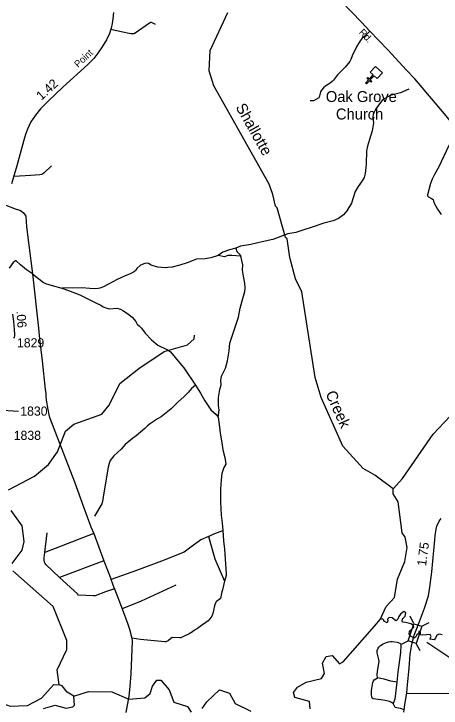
# Model space of a CAD drawing. Extents: x 2104537 to 2336408, y 34176 to 229611.
# Drawn here: x 2200536 to 2206373, y 68278 to 77773 of the extents above; entities that cross this region are included whole.
import ezdxf

# ---------------------------------------------------------------- set-up
doc = ezdxf.new("R2010")
doc.units = 0
for name, color, linetype in [('Exist Cultural Church CELL', 7, 'Continuous'), ('Exist Cultural Church Label', 7, 'Continuous'), ('Exist Hydrographic Creek Single Shore', 7, 'Continuous'), ('Exist Hydrographic Misc Water Feature', 7, 'Continuous'), ('Exist Road Non-System Type 51', 7, 'Continuous'), ('Exist Road Primary NC Attributed', 7, 'Continuous'), ('Exist Road Primary NC Label', 7, 'Continuous'), ('Exist Road Secondary Mileage Hundredths English Label', 7, 'Continuous'), ('Exist Road Secondary Structure Standard Bridge CELL', 7, 'Continuous'), ('Exist Road Secondary Structure Standard Bridge Number Label', 7, 'Continuous'), ('Exist Road Secondary Type 51 Attributed', 7, 'Continuous'), ('Exist Road Secondary Type 51 Label', 7, 'Continuous'), ('Exist Road Secondary Type 51 Number Label', 7, 'Continuous'), ('Old_Level_32', 7, 'Continuous')]:
    doc.layers.add(name, color=color, linetype=linetype)

msp = doc.modelspace()

# ---------------------------------------------------------------- linework, layer by layer
at = {"layer": 'Exist Cultural Church CELL'}
msp.add_lwpolyline([(2205498.5, 76887.3), (2205456.9, 76926.3), (2205404.7, 76870.8), (2205428, 76848.9), (2205417.1, 76837.3), (2205393.8, 76859.2), (2205352.6, 76815.4), (2205340.9, 76826.4), (2205382.1, 76870.2), (2205358.8, 76892.1), (2205369.8, 76903.7), (2205393.1, 76881.8), (2205445.3, 76937.3), (2205403.4, 76976.9), (2205476.3, 77054.4), (2205571.4, 76964.8)], close=True, dxfattribs=at)
at = {"layer": 'Exist Hydrographic Creek Single Shore'}
msp.add_line((2205460.9, 69399.7), (2205539.8, 69490.8), dxfattribs=at)
for points in [[(2205719.8, 71275.4), (2205467.8, 71464), (2205308.9, 71555.6), (2205031.9, 71859.5), (2204735.8, 72524.6), (2204650.9, 72798.6), (2204467.8, 73973.4), (2204383.9, 74148.9), (2204305.8, 74439), (2204270.9, 74695.6), (2204245.9, 74712.6), (2204134.8, 75121.5), (2204109.8, 75144.9), (2204074.9, 75303.1), (2204023.8, 75445.1), (2203265.8, 76788.5), (2203205.9, 76996.3), (2203219.8, 77271.7), (2203458.9, 77792)], [(2205539.8, 69490.8), (2205621.8, 69666.4), (2205737.9, 69792.2), (2205777.9, 70040.7), (2205875.9, 70284.9), (2205907.9, 70474.5), (2205881.8, 70616.1), (2205840, 70676), (2205787.9, 71100.2), (2205719.8, 71206.5), (2205719.8, 71275.4)], [(2206385.7, 69278), (2206350, 69288.8), (2206316, 69274.5), (2206296.3, 69233.3), (2206278.4, 69213.6), (2206217.6, 69219), (2206237.3, 69256.6), (2206222.9, 69283.4), (2206174.6, 69278), (2206117.4, 69274.5), (2206090.6, 69278), (2206092.4, 69306.7), (2206081.6, 69331.7), (2206067.3, 69326.4), (2206062, 69297.7), (2206040.5, 69279.8), (2206028, 69253), (2206004.7, 69233.3), (2205961.8, 69256.6), (2205936.7, 69285.2), (2205942.1, 69328.2), (2205976.1, 69362.2), (2205999.3, 69383.6), (2205994, 69408.7), (2205958.2, 69432), (2205888.4, 69448.1), (2205845.5, 69455.2), (2205840.1, 69467.8), (2205845.5, 69500), (2205881.3, 69534), (2205890.2, 69578.7), (2205863.4, 69598.4), (2205816.9, 69562.6), (2205795.4, 69528.6), (2205782.9, 69492.8), (2205757.8, 69469.6), (2205734.6, 69485.7), (2205702.4, 69514.3), (2205661.3, 69516.1), (2205641.6, 69494.6), (2205643.4, 69469.6), (2205636.2, 69444.5), (2205598.6, 69464.2), (2205587.9, 69483.9), (2205571.8, 69500), (2205539.8, 69490.8)], [(2204581.8, 68265.9), (2204573, 68367.7), (2204372.8, 68424.1), (2204355.8, 68490.1), (2204412.8, 68564.4), (2204529.9, 68634.4), (2204737.8, 68682.8), (2204778.8, 68750.9), (2204752.8, 68892.5), (2204801.8, 68983.4), (2204885.9, 68995), (2204986, 68884.8), (2205036, 68910), (2205460.9, 69399.7)], [(2201356.7, 68442.9), (2201555.8, 68504.7), (2201872.9, 68498.5), (2202106.8, 68398.9), (2202322.9, 68417.7), (2202397.8, 68475.3), (2202429.8, 68576.4), (2202487.8, 68660.6), (2202545.8, 68659.4), (2202655.9, 68529.4), (2202722.8, 68360.8), (2202906.9, 68298.2), (2202957.8, 68221.7)], [(2199594.7, 67682.9), (2199728.8, 67726.3), (2199877.9, 67851.3), (2199992.7, 67983.6), (2200025.7, 68084.7), (2200031.9, 68478.3), (2200097.7, 68526.2), (2200222.8, 68471.3), (2200331.9, 68360.9), (2200482.8, 68305.5), (2200723.7, 68314), (2200914.8, 68415.3), (2201079.9, 68599.1), (2201155.8, 68594.4)], [(2201356.7, 68442.9), (2201264.9, 68493.9), (2201196.8, 68583.7), (2201155.8, 68594.4)], [(2203106.9, 68274.6), (2203172.9, 68365.2), (2203346.8, 68525.9), (2203480.9, 68484), (2203556.9, 68341.4), (2203773.9, 68235.6)]]:
    msp.add_lwpolyline(points, dxfattribs=at)
at = {"layer": 'Exist Hydrographic Misc Water Feature'}
for points in [[(2205719.8, 71275.4), (2205843.9, 71417.4), (2206263.8, 72026), (2206496, 72270.9), (2206860.9, 72513.2), (2207050.8, 72749), (2207522.9, 73077.9), (2208394.9, 73543.3), (2209201, 73846)], [(2200461.9, 71262), (2200818.9, 71448.7), (2201009.8, 71609), (2201133.8, 71783.8), (2201239.9, 72067.2), (2201355.9, 72160.1), (2201737.7, 72297.1), (2201836.8, 72423.1), (2201984.8, 72715.5), (2202241.7, 72923.8), (2202590.7, 73153.3), (2202906.9, 73245.6), (2202997.8, 73329.1), (2203005.8, 73378.2)], [(2200510.9, 70253.8), (2200650.7, 70438.1), (2200674.7, 70555.8), (2200648.9, 70772.8), (2200497.8, 70979.1)], [(2201155.8, 68594.4), (2201128.9, 68801.6), (2201259.7, 69077.9), (2201259.7, 69202.6), (2201072.7, 69665.6), (2200519.7, 70155.2)], [(2200940.9, 68273.7), (2201098.8, 68316.6), (2201248.9, 68277.7), (2201340.7, 68295.5), (2201365.8, 68318), (2201356.7, 68442.9)]]:
    msp.add_lwpolyline(points, dxfattribs=at)
at = {"layer": 'Exist Road Non-System Type 51'}
for p, q in [((2200741.2, 74609.7), (2200789.1, 74219.1)), ((2200957.3, 70405.6), (2200991.7, 70676.2)), ((2201626, 70664.3), (2200957.3, 70405.6)), ((2201626, 70664.3), (2201762.8, 70292)), ((2201762.8, 70292), (2201157.7, 70064.5)), ((2201762.8, 70292), (2201866.5, 70035.4)), ((2201912.3, 69908.2), (2201866.5, 70035.4)), ((2201912.3, 69908.2), (2202013.7, 69637.5))]:
    msp.add_line(p, q, dxfattribs=at)
for points in [[(2202470.6, 77628.9), (2202417.4, 77656.2), (2202403.6, 77656.1), (2202178.1, 77501), (2202167.9, 77498.6), (2202134.2, 77500.5), (2202001.5, 77526.7), (2201861, 77559)], [(2205398.3, 77538.9), (2205329.3, 77468.1), (2205295.6, 77439.6), (2205268, 77403), (2205217.2, 77320.7), (2205158.8, 77199.7), (2205138.4, 77147.3), (2205124.5, 77123.6), (2205062.9, 77042.5), (2204958.3, 76941.2), (2204901, 76864.5), (2204885.3, 76848.1), (2204857.6, 76826), (2204797.9, 76789.1), (2204766.5, 76762.8), (2204737, 76728.2), (2204725.1, 76708.1), (2204707.9, 76634.3), (2204702.2, 76623.9), (2204630.5, 76585), (2204584.9, 76582.2)], [(2205933, 76742.8), (2205818.2, 76692.7), (2205676.8, 76655.3), (2205572.1, 76596.3), (2205481.9, 76474.8), (2205445.1, 76403.5), (2205439.5, 76354.4), (2205447.3, 76280.9), (2205430.6, 76172.8), (2205396.1, 76054.6), (2205367.1, 75965.5), (2205353.8, 75902), (2205347.1, 75719.7), (2205343.7, 75672.9), (2205337.1, 75591.6), (2205320.4, 75534.7), (2205294.7, 75487.9), (2205239, 75409.9), (2205197.8, 75342.5), (2205146.6, 75184.2), (2205085.3, 75077.2), (2205040.8, 75024.9), (2204969.5, 74972.5), (2204899.3, 74942.4), (2204771.2, 74910.1), (2204612, 74855.4), (2204483.9, 74814.2), (2204387, 74783), (2204277.8, 74762.9), (2204075.1, 74689.4), (2203925.8, 74654.3), (2203771, 74620.8), (2203631.8, 74597.4), (2203568.3, 74568.5)], [(2206686.2, 76069.6), (2206596.8, 76028.3), (2206509.2, 75993.3), (2206485.3, 75979), (2206467.5, 75956.7), (2206442.3, 75896.5), (2206343, 75679.2), (2206282.3, 75578.4), (2206251.3, 75514), (2206228.1, 75453.8), (2206207.4, 75365.6), (2206186, 75297.1), (2206186.5, 75285), (2206199.7, 75272.9), (2206242.9, 75250.1), (2206262.3, 75235.6), (2206275.6, 75194.3), (2206300.2, 75144.6), (2206325, 75100.9), (2206373.8, 75027.7)], [(2201047.5, 75696.7), (2200950.9, 75599.2), (2200924.9, 75581), (2200911.1, 75576.7), (2200889, 75572.5), (2200761.1, 75560.9), (2200537.5, 75548.1)], [(2200426.6, 75156.6), (2200567.3, 75102.3), (2200616.2, 75086.3), (2200637.6, 75073.4), (2200666, 75051.6), (2200690.4, 75021.9), (2200697.3, 75004.4), (2200710.3, 74862.4), (2200741.2, 74609.7)], [(2203568.3, 74568.5), (2203480.3, 74547.3), (2203392.9, 74514.6), (2203324.9, 74468.1)], [(2203568.3, 74568.5), (2203583.9, 74523.9), (2203628.4, 74477.1), (2203638.3, 74459.8)], [(2203324.9, 74468.1), (2203228.7, 74438.3), (2203150.8, 74421.7), (2203029.8, 74418.4), (2202903.4, 74366.7), (2202804.1, 74337.4), (2202698.3, 74309.9), (2202640.4, 74303.2), (2202601.3, 74301.6), (2202552.4, 74302.3), (2202502.4, 74309.5), (2202426, 74331.3), (2202413.7, 74336.1), (2202375.7, 74360.4), (2202355.8, 74364.4), (2202325.5, 74359.1), (2202267.6, 74334.3), (2202216.3, 74292), (2202196.7, 74263.5), (2202181.7, 74248.1), (2202169, 74239.1), (2202115.3, 74212.3), (2202055.6, 74191.8), (2201946.3, 74140.4), (2201761.3, 74041.9), (2201709.8, 74021.3), (2201685.7, 74014.8), (2201631.9, 74013.3), (2201459.8, 74024.1), (2201191.4, 74022.4)], [(2203638.3, 74459.8), (2203512.3, 74466.5), (2203459.2, 74466.5), (2203414.4, 74449.9), (2203324.9, 74468.1)], [(2203326.6, 72256.8), (2203331.5, 72288.3), (2203341.5, 72359.6), (2203331.5, 72411), (2203331.5, 72523.8), (2203349.8, 72635), (2203368, 72700.5), (2203364.7, 72758.6), (2203373, 72818.3), (2203426, 72926.1), (2203452.6, 73025.7), (2203475.8, 73163.4), (2203485.7, 73268.7), (2203605.1, 73625.4), (2203628.3, 73746.5), (2203653.2, 73847.7), (2203691.3, 73973.8), (2203696.3, 74020.2), (2203691.3, 74089.9), (2203674.7, 74186.1), (2203659.8, 74265.7), (2203664.8, 74338.7), (2203638.3, 74459.8)], [(2200789.1, 74219.1), (2200708.1, 74272.2), (2200627.3, 74339.1), (2200568.4, 74394.3), (2200558.2, 74394.2), (2200538, 74383.8), (2200524.6, 74371.5), (2200472, 74295.1)], [(2200789.1, 74219.1), (2200942.6, 74099.4), (2200968.9, 74083.8), (2201059.2, 74056.8), (2201191.4, 74022.4)], [(2200789.1, 74219.1), (2200870.9, 73476.4), (2200884.1, 73327.2), (2200920.6, 73027), (2200961.9, 72635.8), (2200970.4, 72583.8), (2200970.8, 72549.7), (2200977.8, 72489.8), (2200999.6, 72360.1), (2201014.6, 72290.3), (2201027.2, 72245.1), (2201246.6, 71677.5), (2201362.7, 71370.9), (2201485.1, 71030.6), (2201586.8, 70757.9), (2201626, 70664.3)], [(2201191.4, 74022.4), (2201282, 73991.8), (2201435, 73929.8), (2201507.5, 73892.6), (2201582, 73859.4), (2201656.4, 73822.5), (2201722.6, 73787.4), (2201757.3, 73765.8), (2201803.5, 73746.5), (2201824.1, 73741.2), (2201839.5, 73740.9), (2201943.3, 73746.4), (2201974.4, 73740.6), (2201991.6, 73734.7), (2202023.8, 73717.3), (2202089.9, 73677), (2202153.2, 73623), (2202200.7, 73566.9), (2202222, 73531.1), (2202246.7, 73504.4), (2202277.3, 73476.5), (2202330.1, 73407.3), (2202417.2, 73314.4), (2202504.1, 73243.5), (2202633.1, 73179.3), (2202658.1, 73164.4), (2202675.6, 73150), (2202801.5, 72997.3), (2202858.4, 72932.2), (2203015.9, 72696.2)], [(2203015.9, 72696.2), (2202964.1, 72647.7), (2202923.8, 72600.9), (2202855.9, 72534.3), (2202778.5, 72467.2), (2202685.8, 72369.9), (2202549.2, 72262.3), (2202497.4, 72233.5), (2202400.5, 72172.3), (2202360.8, 72139.6), (2202323.3, 72101.3), (2202265.9, 72050.6), (2202204.6, 72001.6), (2202155, 71965.1), (2202054, 71883.8), (2202001, 71821.1), (2201902.1, 71727.9), (2201852.6, 71665.2), (2201836.1, 71622.2), (2201822.3, 71571), (2201765, 71220.1), (2201748.3, 71101.9), (2201738.8, 71069.6), (2201638.8, 70904.6)], [(2203015.9, 72696.2), (2203085, 72587.3), (2203144.6, 72482.1), (2203226.2, 72359.2), (2203298.4, 72291.6), (2203326.6, 72256.8)], [(2203326.6, 72256.8), (2203343.1, 72119.9), (2203356.4, 72038.6), (2203378, 71907.5), (2203392.9, 71811.3), (2203419.4, 71706.8), (2203427.7, 71647.9), (2203429.4, 71614.7), (2203406.1, 71569.9), (2203377, 71486.2), (2203368.8, 71400.7), (2203358.5, 71270.7), (2203356.8, 71098.8), (2203369.3, 70916.8), (2203382.7, 70808.9), (2203390.7, 70707)], [(2203195.8, 70626.7), (2203258.8, 70658.2), (2203390.7, 70707)], [(2203390.7, 70707), (2203401.9, 70563.5), (2203413.5, 70451.4), (2203435.9, 70113.7), (2203434.1, 70089.8), (2203415.6, 70015.2)], [(2203195.8, 70626.7), (2203088.5, 70577.3), (2202969.4, 70493.8), (2202863.8, 70410.3), (2202782.1, 70378), (2202589.7, 70301.3), (2202210, 70159.9), (2201866.5, 70035.4)], [(2203195.8, 70626.7), (2203282.6, 70317.5), (2203415.6, 70015.2)], [(2201157.7, 70064.5), (2200973.5, 70243.9), (2200963.3, 70257.8), (2200955.1, 70275.7), (2200951.2, 70294.5), (2200950.3, 70331.6), (2200957.3, 70405.6)], [(2201912.3, 69908.2), (2201786.8, 69866.3), (2201647.3, 69813.9), (2201619.4, 69812.1), (2201417.2, 69823.9), (2201404.7, 69839.5), (2201157.7, 70064.5)], [(2203415.6, 70015.2), (2203386.4, 69897.1), (2203377, 69867.1), (2203359.2, 69777.6), (2203354.5, 69771.1), (2203302.9, 69736), (2203296.9, 69727.9), (2203275.5, 69675.9), (2203255.1, 69569.6), (2203239.4, 69537.4), (2203212.1, 69497), (2203188.6, 69469.9), (2203158.6, 69446.5), (2203101.1, 69407.6), (2203043.8, 69364.7), (2203003.7, 69342.5), (2202976.4, 69319.8), (2202930.5, 69291.4), (2202845.1, 69251.1), (2202815.4, 69239.9), (2202803.2, 69237.8), (2202696.7, 69242.5), (2202679.4, 69232), (2202641.7, 69197.6), (2202612.9, 69184.4), (2202598.7, 69183), (2202265.4, 69216.7), (2202147.3, 69233.4)], [(2202747.9, 69959), (2202276.5, 69740.7), (2202013.7, 69637.5)], [(2202013.7, 69637.5), (2202094.5, 69424.4), (2202117.5, 69357), (2202147.3, 69233.4)], [(2202147.3, 69233.4), (2202153.7, 69191.3), (2202133.6, 68747.1), (2202121.8, 68573.1), (2202104.8, 68443.2), (2202067.5, 68218.9)], [(2205503.3, 68692.6), (2205500.5, 68736.7), (2205504.2, 68776.6), (2205526.3, 68918.9), (2205519.5, 68958.7), (2205499, 69034.9), (2205499.6, 69063.8), (2205511.8, 69099), (2205521.5, 69112.9), (2205545.2, 69133.1), (2205582.7, 69155.3), (2205624.8, 69176.2), (2205653.5, 69186.1), (2205681.8, 69189.9), (2205703.1, 69188.8), (2205774.8, 69178.2), (2205807.3, 69164.5), (2205816.7, 69158.1), (2205820.8, 69151.7), (2205821.7, 69126.8), (2205821.1, 69104.9)], [(2205816, 69037.1), (2205780, 68770.3), (2205770.1, 68632.4)], [(2205821.1, 69104.9), (2205820.2, 69068.7), (2205816, 69037.1)], [(2205715.7, 68341.3), (2205694.7, 68352.7), (2205665.6, 68367.2), (2205608.9, 68380.2), (2205549.1, 68389.9), (2205446.9, 68406), (2205433, 68415.8), (2205427.3, 68426.7), (2205422.4, 68461.6), (2205423.5, 68517.7), (2205438.1, 68629.9), (2205447.7, 68652.1), (2205459.5, 68666.3), (2205503.3, 68692.6)], [(2205770.1, 68632.4), (2205711.9, 68639.4), (2205686.1, 68645.2), (2205595.4, 68674.1), (2205503.3, 68692.6)], [(2205770.1, 68632.4), (2205741.1, 68402), (2205715.7, 68341.3)], [(2205904, 68484.1), (2206556.4, 68478.1), (2206698, 68476)], [(2205869.1, 68253.3), (2205816, 68271.7), (2205791.8, 68276.6), (2205765.9, 68279.8), (2205746.5, 68284.7), (2205715.7, 68341.3)]]:
    msp.add_lwpolyline(points, dxfattribs=at)
at = {"layer": 'Exist Road Primary NC Attributed'}
msp.add_lwpolyline([(2209055.5, 73978.4), (2209037.8, 74012.2), (2208614.2, 74282.8), (2208495.2, 74369.1), (2208293.4, 74488.5), (2208051.3, 74643.4), (2207851.6, 74782.7), (2207754.6, 74855.5), (2207669.3, 74924.4), (2207629, 74961.9), (2207423.6, 75199.1), (2206686.2, 76069.6), (2206439.8, 76378.5), (2206015.2, 76882.7), (2205901.3, 77001.4), (2205643.9, 77280), (2205398.3, 77538.9), (2205284.5, 77661.5), (2204864.8, 78097.8), (2204647.8, 78329)], dxfattribs=at)
at = {"layer": 'Exist Road Secondary Structure Standard Bridge CELL'}
for p, q in [((2206002.3, 69432.1), (2205951.2, 69533.2)), ((2206109.8, 69396.8), (2206210.8, 69447.9)), ((2205823.3, 69145.8), (2205924.4, 69196.8)), ((2206085.4, 69059.7), (2206034.4, 69160.7))]:
    msp.add_line(p, q, dxfattribs=at)
msp.add_lwpolyline([(2205924.4, 69196.8), (2206001.7, 69432.3), (2206111.7, 69396.2), (2206034.4, 69160.7)], close=True, dxfattribs=at)
at = {"layer": 'Exist Road Secondary Structure Standard Bridge Number Label'}
msp.add_line((2206177.6, 69177.4), (2206892.7, 68704.9), dxfattribs=at)
at = {"layer": 'Exist Road Secondary Type 51 Attributed'}
for points in [[(2201898.9, 77793.9), (2201889, 77704.8), (2201879.1, 77641.6), (2201865.2, 77576), (2201841.5, 77504.9), (2201800.1, 77416.3), (2201742.6, 77321.2), (2201683.2, 77234.1), (2201627.8, 77164.7), (2201546.6, 77079.6), (2201204, 76768.5), (2201003.9, 76580.1), (2200901.1, 76475.1), (2200829.8, 76389.9), (2200798.1, 76344.4), (2200768.4, 76294.9), (2200720.9, 76196.1), (2200693.6, 76124.2), (2200671.4, 76043.7), (2200576.3, 75695), (2200501.1, 75449.3)], [(2200516.2, 73663.7), (2200529.6, 73564), (2200541.7, 73455.9), (2200544, 73386.3), (2200544, 73370.2), (2200537.4, 73349.6), (2200531.9, 73338.6)], [(2205996.8, 69237.6), (2206007.1, 69273.4), (2206051.9, 69390.5), (2206143.9, 69645.8), (2206198.7, 69813.1), (2206219.4, 69933.4), (2206244.5, 70143.2), (2206288.3, 70578.1), (2206291.7, 70634.1), (2206304.6, 70726.4), (2206314.2, 70764.6), (2206347.7, 70836.8), (2206375, 70871)], [(2205864.7, 68223.5), (2205884.1, 68353), (2205904.5, 68488.6), (2205914.5, 68596.1), (2205932.4, 68778.2), (2205940.7, 68881.1), (2205946.6, 68957.2), (2205952.4, 69011.9), (2205964.1, 69095.8), (2205970, 69127), (2205987.7, 69206), (2205996.8, 69237.6)]]:
    msp.add_lwpolyline(points, dxfattribs=at)
at = {"layer": 'Exist Road Secondary Type 51 Number Label'}
msp.add_line((2199919.2, 72382.9), (2200598.5, 72337), dxfattribs=at)

# ---------------------------------------------------------------- texts
at = {"layer": 'Exist Cultural Church Label'}
for s, p in [('Oak Grove', (2204798.2, 76567.4)), ('Church', (2204936, 76328.4))]:
    msp.add_text(s, height=150, dxfattribs=at).set_placement(p)
at = {"layer": 'Exist Road Primary NC Label'}
msp.add_text('Rd.', height=95, rotation=313.48542, dxfattribs=at).set_placement((2205243.4, 77513.6))
at = {"layer": 'Exist Road Secondary Mileage Hundredths English Label'}
for s, rotation, p in [('1.42', 42.23693, (2200910.7, 76583.5)), ('.06', 273.53882, (2200571.1, 73706.3)), ('1.75', 82.52042, (2206166.9, 70214.8))]:
    msp.add_text(s, height=125, rotation=rotation, dxfattribs=at).set_placement(p)
at = {"layer": 'Exist Road Secondary Type 51 Label'}
msp.add_text('Point', height=95, rotation=42.7211, dxfattribs=at).set_placement((2201412.9, 77031.8))
at = {"layer": 'Exist Road Secondary Type 51 Number Label'}
for s, p in [('1829', (2200578.4, 73211.6)), ('1830', (2200623.4, 72277.5)), ('1838', (2200533.9, 71945.8))]:
    msp.add_text(s, height=125, dxfattribs=at).set_placement(p)
at = {"layer": 'Old_Level_32'}
for s, rotation, p in [('Shallotte', 299.43725, (2203561, 76497.9)), ('Creek', 293.99691, (2204789.9, 72580.6))]:
    msp.add_text(s, height=150, rotation=rotation, dxfattribs=at).set_placement(p)

doc.saveas('drawing.dxf')
